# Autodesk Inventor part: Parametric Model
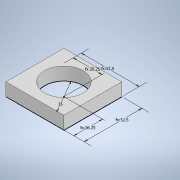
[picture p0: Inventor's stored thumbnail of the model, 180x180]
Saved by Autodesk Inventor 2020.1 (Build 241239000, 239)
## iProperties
Created: 2019-09
Part Number: Parametric Model
Material: Generic
Document SubType Name: Modeling
Designer: Synergysoft Dell02
Density: 1 g/cm^3
Appearance: Default
Author: Synergysoft Dell02
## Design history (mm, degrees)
sketch "Sketch1"
  geometry: L1 (0, 0)-(-52.5, 0); L2 (-52.5, 0)-(-52.5, -52.5); L3 (-52.5, -52.5)-(0, -52.5); L4 (0, -52.5)-(0, 0); C1 r 17.5 at (-26.25, -26.25)
  constraints: 8 end point, 2 parallel, 1 centre point, 1 horizontal, 1 horizontal alignment, 1 perpendicular, 1 vertical alignment, 1 other
  dimensions: "d3" = 26.25 distance from line of C1.centre L4 (derived); "d4" = 26.25 distance from line of L1 C1.centre (derived)
extrude "Extrusion1" new body sketch "Sketch1" taper "d6" = 0 deg
body "Solid1"
